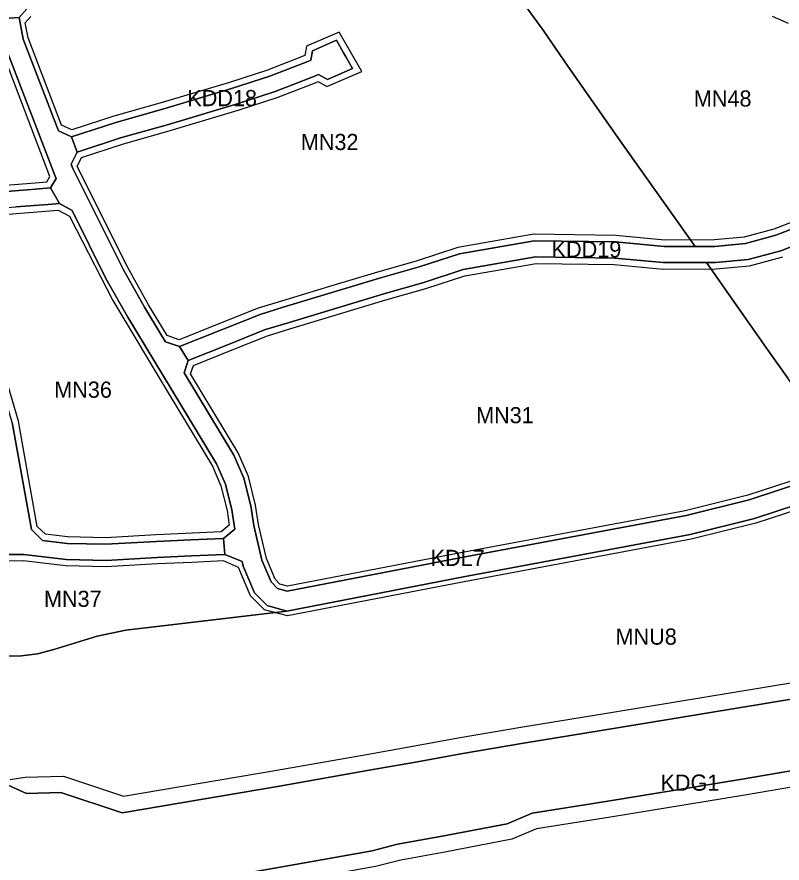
# Model space of a CAD drawing. Extents: x 7440055 to 7442242, y 5549003 to 5552256.
# Drawn here: x 7440932 to 7441405, y 5549569 to 5550092 of the extents above; entities that cross this region are included whole.
import ezdxf

# ---------------------------------------------------------------- set-up
doc = ezdxf.new("R2010")
doc.units = 0
for name, color, linetype in [('linie_rozgraniczajace', 7, 'Continuous'), ('linie_zabudowy_nieprzekraczalne', 7, 'Continuous'), ('oznaczenia_przeznaczen', 7, 'Continuous')]:
    doc.layers.add(name, color=color, linetype=linetype)

msp = doc.modelspace()

# ---------------------------------------------------------------- linework, layer by layer
at = {"layer": 'linie_rozgraniczajace'}
for points in [[(7441244.66, 5550101.57), (7441257.4, 5550083.89), (7441272.75, 5550061.72), (7441288.11, 5550039.55), (7441305.11, 5550015.41), (7441322.11, 5549991.27), (7441351.43, 5549950.16), (7441332.19, 5549950.12), (7441302.19, 5549952.9), (7441251.88, 5549953.71), (7441205.54, 5549945.54), (7441180.69, 5549937.47), (7441156.09, 5549930.49), (7441096.6, 5549912.51), (7441082.34, 5549908.12), (7441057.34, 5549898.15), (7441032.35, 5549888.19), (7441023.63, 5549891.17), (7441021.01, 5549895.49), (7441010.69, 5549912.54), (7440997.68, 5549935.61), (7440966.39, 5549998.44), (7440965.36, 5550001.13), (7440968.96, 5550008.55), (7440995.87, 5550017.35), (7441025.56, 5550025.67), (7441067.52, 5550038.25), (7441091.52, 5550046), (7441115.5, 5550055.3), (7441118.48, 5550056.6), (7441123.9, 5550053.49), (7441139.47, 5550060.24), (7441135, 5550067.98), (7441133.96, 5550069.96), (7441129.54, 5550077.73), (7441114.6, 5550071.26), (7441113.57, 5550065.36), (7441111.7, 5550064.56), (7441088.18, 5550055.43), (7441064.55, 5550047.8), (7441022.78, 5550035.28), (7440992.96, 5550026.92), (7440965.52, 5550017.95), (7440957.49, 5550021.69), (7440935.75, 5550078.45), (7440933.14, 5550091.88), (7440937.99, 5550097.18)], [(7441411.06, 5550092.87), (7441419.58, 5550088.95), (7441428.98, 5550084.13), (7441435.04, 5550080.83), (7441445.51, 5550074.75), (7441485.64, 5550051.12), (7441493.91, 5550042.46), (7441494.16, 5550031.09), (7441441.35, 5549976.89), (7441420.1, 5549964.26), (7441401.34, 5549957.05), (7441382.54, 5549951.99), (7441363.61, 5549950.18), (7441351.43, 5549950.16), (7441322.11, 5549991.27), (7441305.11, 5550015.41), (7441288.11, 5550039.55), (7441272.75, 5550061.72), (7441257.4, 5550083.89), (7441244.66, 5550101.57)], [(7440937.99, 5550097.18), (7440933.14, 5550091.88), (7440921.08, 5550091.06), (7440913.88, 5550095.55), (7440787.47, 5550086.98), (7440782.28, 5550081.64), (7440772.28, 5550080.96), (7440765.42, 5550085.49), (7440743.79, 5550084.03), (7440738.28, 5550083.8), (7440736.27, 5550083.77)], [(7440921.08, 5550091.06), (7440933.14, 5550091.88), (7440935.75, 5550078.45), (7440957.49, 5550021.69), (7440965.52, 5550017.95), (7440968.96, 5550008.55), (7440965.36, 5550001.13), (7440966.39, 5549998.44), (7440997.68, 5549935.61), (7441010.69, 5549912.54), (7441021.01, 5549895.49), (7441023.63, 5549891.17), (7441032.35, 5549888.19), (7441037.76, 5549879.58), (7441035.24, 5549871.98), (7441066.05, 5549821.08), (7441072.24, 5549806.85), (7441076.53, 5549789.57), (7441078.31, 5549777.44), (7441083.32, 5549756.08), (7441089.01, 5549742.53), (7441092.92, 5549738.59), (7441099.04, 5549736.87), (7441205.81, 5549757.44), (7441345.8, 5549783.58), (7441384.91, 5549793.35), (7441419.28, 5549804.6)], [(7440924.17, 5550075.14), (7440955.39, 5549993.61), (7440956.09, 5549992.21), (7440952.64, 5549986.34), (7440943.35, 5549985.58), (7440917.23, 5549983.48)], [(7441414.65, 5549790.45), (7441388.23, 5549781.81), (7441348.36, 5549771.85), (7441208.05, 5549745.65), (7441098.76, 5549724.49), (7441086.62, 5549727.89), (7441078.85, 5549735.74), (7441071.87, 5549752.37), (7441071.22, 5549755.14), (7441060.41, 5549759.56), (7441059.61, 5549769.53), (7441066.52, 5549775.2), (7441064.74, 5549787.25), (7441060.84, 5549802.98), (7441055.37, 5549815.55), (7441000.33, 5549906.48), (7440987.07, 5549929.99), (7440965.97, 5549972.37), (7440958.2, 5549976.76), (7440952.64, 5549986.34), (7440956.09, 5549992.21), (7440955.39, 5549993.61), (7440924.17, 5550075.14)], [(7440917.23, 5549983.48), (7440943.35, 5549985.58), (7440952.64, 5549986.34), (7440958.2, 5549976.76), (7440951.18, 5549976.19), (7440931.08, 5549974.56)], [(7441424.48, 5549955.23), (7441404.44, 5549947.53), (7441384.33, 5549942.11), (7441364.1, 5549940.19), (7441358.42, 5549940.18), (7441331.74, 5549940.12), (7441301.65, 5549942.91), (7441252.68, 5549943.69), (7441207.96, 5549935.82), (7441183.6, 5549927.9), (7441158.9, 5549920.9), (7441099.52, 5549902.95), (7441085.67, 5549898.68), (7441085.06, 5549898.5), (7441061.72, 5549889.13), (7441037.76, 5549879.58), (7441032.35, 5549888.19), (7441057.34, 5549898.15), (7441082.34, 5549908.12), (7441096.6, 5549912.51), (7441156.09, 5549930.49), (7441180.69, 5549937.47), (7441205.54, 5549945.54), (7441251.88, 5549953.71), (7441302.19, 5549952.9), (7441332.19, 5549950.12), (7441351.43, 5549950.16), (7441363.61, 5549950.18), (7441382.54, 5549951.99), (7441401.34, 5549957.05), (7441420.1, 5549964.26)], [(7441419.28, 5549804.6), (7441384.91, 5549793.35), (7441345.8, 5549783.58), (7441205.81, 5549757.44), (7441099.04, 5549736.87), (7441092.92, 5549738.59), (7441089.01, 5549742.53), (7441083.32, 5549756.08), (7441078.31, 5549777.44), (7441076.53, 5549789.57), (7441072.24, 5549806.85), (7441066.05, 5549821.08), (7441035.24, 5549871.98), (7441037.76, 5549879.58), (7441061.72, 5549889.13), (7441085.06, 5549898.5), (7441085.67, 5549898.68), (7441099.52, 5549902.95), (7441158.9, 5549920.9), (7441183.6, 5549927.9), (7441207.96, 5549935.82), (7441252.68, 5549943.69), (7441301.65, 5549942.91), (7441331.74, 5549940.12), (7441358.42, 5549940.18), (7441382.53, 5549905.82), (7441395.68, 5549887.23), (7441408.82, 5549868.65)], [(7440928.76, 5549841.19), (7440940.71, 5549774.91), (7440947.63, 5549768.24), (7440962.89, 5549766.41), (7440986.73, 5549765.88), (7441018.11, 5549767.68), (7441039.41, 5549768.65), (7441059.61, 5549769.53), (7441060.41, 5549759.56), (7441039.86, 5549758.66), (7441018.62, 5549757.69), (7440986.91, 5549755.88), (7440962.18, 5549756.42), (7440936, 5549759.56), (7440910.98, 5549759.5)], [(7440926.69, 5549696.68), (7440934.53, 5549696.82), (7440944.59, 5549697.98), (7440954.59, 5549700.82), (7440981.5, 5549708.94), (7440999.24, 5549712.67), (7441098.76, 5549724.49), (7441208.05, 5549745.65), (7441348.36, 5549771.85), (7441388.23, 5549781.81), (7441414.65, 5549790.45)], [(7440910.98, 5549759.5), (7440936, 5549759.56), (7440962.18, 5549756.42), (7440986.91, 5549755.88), (7441018.62, 5549757.69), (7441039.86, 5549758.66), (7441060.41, 5549759.56), (7441071.22, 5549755.14), (7441071.87, 5549752.37), (7441078.85, 5549735.74), (7441086.62, 5549727.89), (7441098.76, 5549724.49), (7440999.24, 5549712.67), (7440981.5, 5549708.94), (7440954.59, 5549700.82), (7440944.59, 5549697.98), (7440934.53, 5549696.82), (7440926.69, 5549696.68)], [(7440802.48, 5549567), (7440823.23, 5549572.15), (7440843.5, 5549575.3), (7440855.84, 5549576.74), (7440884.44, 5549597.32), (7440908.45, 5549606.4), (7440914.7, 5549614.65), (7440924.18, 5549617.76), (7440937.73, 5549611.73), (7440959.03, 5549612.31), (7440997, 5549599.66), (7441094.31, 5549616.16), (7441149.75, 5549626.01), (7441179.57, 5549631.34), (7441206.47, 5549636.19), (7441246.5, 5549643.08), (7441303.43, 5549652.3), (7441394.72, 5549667.37), (7441442.22, 5549675.26)], [(7441442.22, 5549675.26), (7441394.72, 5549667.37), (7441303.43, 5549652.3), (7441246.5, 5549643.08), (7441206.47, 5549636.19), (7441179.57, 5549631.34), (7441149.75, 5549626.01), (7441094.31, 5549616.16), (7440997, 5549599.66), (7440959.03, 5549612.31), (7440937.73, 5549611.73), (7440924.18, 5549617.76)], [(7441077.17, 5549562.92), (7441114.4, 5549569.57), (7441151.63, 5549576.22), (7441167.26, 5549580.22), (7441194.82, 5549585.27), (7441235.03, 5549592.94), (7441250.56, 5549599.46), (7441297.44, 5549606.92), (7441339.01, 5549613.71), (7441380.59, 5549620.51), (7441416.63, 5549626.68)], [(7441416.63, 5549626.68), (7441380.59, 5549620.51)], [(7441380.59, 5549620.51), (7441339.01, 5549613.71), (7441297.44, 5549606.92), (7441250.56, 5549599.46), (7441235.03, 5549592.94), (7441194.82, 5549585.27), (7441167.26, 5549580.22), (7441151.63, 5549576.22), (7441114.4, 5549569.57), (7441077.17, 5549562.92)]]:
    msp.add_lwpolyline(points, dxfattribs=at)
for points in [[(7440965.52, 5550017.95), (7440992.96, 5550026.92), (7441022.78, 5550035.28), (7441064.55, 5550047.8), (7441088.18, 5550055.43), (7441111.7, 5550064.56), (7441113.57, 5550065.36), (7441114.6, 5550071.26), (7441129.54, 5550077.73), (7441133.96, 5550069.96), (7441135, 5550067.98), (7441139.47, 5550060.24), (7441123.9, 5550053.49), (7441118.48, 5550056.6), (7441115.5, 5550055.3), (7441091.52, 5550046), (7441067.52, 5550038.25), (7441025.56, 5550025.67), (7440995.87, 5550017.35), (7440968.96, 5550008.55)], [(7441358.42, 5549940.18), (7441364.1, 5549940.19), (7441384.33, 5549942.11), (7441404.44, 5549947.53), (7441424.48, 5549955.23), (7441447.59, 5549968.97), (7441501.33, 5550023.93), (7441512.47, 5550024.21), (7441597.49, 5549942.15), (7441597.49, 5549930.9), (7441547.82, 5549887.51), (7441530.17, 5549873.25), (7441499.57, 5549847.44), (7441470.08, 5549827.43), (7441446.19, 5549815.48), (7441420.8, 5549851.6), (7441408.82, 5549868.65), (7441395.68, 5549887.23), (7441382.53, 5549905.82)], [(7440888.56, 5549966.4), (7440891.9, 5549971.51), (7440904.95, 5549972.51), (7440931.08, 5549974.56), (7440951.18, 5549976.19), (7440958.2, 5549976.76), (7440965.97, 5549972.37), (7440987.07, 5549929.99), (7441000.33, 5549906.48), (7441055.37, 5549815.55), (7441060.84, 5549802.98), (7441064.74, 5549787.25), (7441066.52, 5549775.2), (7441059.61, 5549769.53), (7441039.41, 5549768.65), (7441018.11, 5549767.68), (7440986.73, 5549765.88), (7440962.89, 5549766.41), (7440947.63, 5549768.24), (7440940.71, 5549774.91), (7440928.76, 5549841.19), (7440908.02, 5549911.96), (7440897.45, 5549940.84)]]:
    msp.add_lwpolyline(points, close=True, dxfattribs=at)
at = {"layer": 'linie_zabudowy_nieprzekraczalne'}
for points in [[(7441118.23, 5550052.13), (7441123.64, 5550049.03), (7441145.15, 5550058.33), (7441131.25, 5550082.83), (7441111.04, 5550074.08), (7441110.02, 5550068.27), (7441086.83, 5550059.2), (7441063.36, 5550051.62), (7441021.66, 5550039.12), (7440991.8, 5550030.75), (7440965.78, 5550022.24), (7440959.34, 5550025.24), (7440938.64, 5550079.28), (7440936.85, 5550088.53), (7440940.33, 5550092.33)], [(7441399, 5550092.55), (7441409.04, 5550088.3)], [(7440916.91, 5549987.47), (7440943.03, 5549989.57), (7440950.24, 5549990.15), (7440952.22, 5549993.51), (7440921.27, 5550074.31)], [(7441418.35, 5549967.87), (7441400.1, 5549960.86), (7441381.83, 5549955.94), (7441363.42, 5549954.18), (7441332.38, 5549954.12), (7441302.41, 5549956.9), (7441251.57, 5549957.71), (7441204.57, 5549949.43), (7441191.92, 5549945.32), (7441179.53, 5549941.3), (7441167.25, 5549937.82), (7441154.97, 5549934.33), (7441125.2, 5549925.34), (7441095.43, 5549916.34), (7441080.96, 5549911.88), (7441056.63, 5549902.18), (7441032.24, 5549892.45), (7441024.82, 5549894.99), (7441021.89, 5549899.83), (7441013.28, 5549914.05), (7441000.33, 5549937.02), (7440969.11, 5549999.7), (7440971.82, 5550005.28), (7440997.03, 5550013.52), (7441026.68, 5550021.83), (7441068.71, 5550034.43), (7441092.86, 5550042.23), (7441117.02, 5550051.6), (7441118.23, 5550052.13)], [(7441063.13, 5549777.59), (7441058.11, 5549773.47), (7441017.9, 5549771.67), (7440986.66, 5549769.89), (7440963.18, 5549770.4), (7440949.44, 5549772.05), (7440944.41, 5549776.89), (7440932.66, 5549842.11), (7440911.82, 5549913.21), (7440901.22, 5549942.18), (7440892.98, 5549965.86), (7440894.17, 5549967.67), (7440918.33, 5549969.52), (7440957.32, 5549972.66), (7440964.4, 5549968.79), (7440968.56, 5549960.44), (7440991.08, 5549916.78), (7441025.28, 5549859.47), (7441052.7, 5549814.17), (7441057.99, 5549802.02), (7441061.79, 5549786.66), (7441063.13, 5549777.59)], [(7441208.93, 5549931.92), (7441253, 5549939.69), (7441301.43, 5549938.91), (7441331.56, 5549936.12), (7441364.29, 5549936.19), (7441385.04, 5549938.16), (7441405.68, 5549943.72)], [(7441418.25, 5549807.42), (7441384.08, 5549796.23), (7441345.17, 5549786.51), (7441205.25, 5549760.39), (7441099.17, 5549739.95), (7441094.49, 5549741.26), (7441091.55, 5549744.23), (7441086.19, 5549757.01), (7441081.26, 5549778.01), (7441079.47, 5549790.15), (7441075.09, 5549807.81), (7441068.72, 5549822.46), (7441039.2, 5549871.23), (7441040.97, 5549876.56), (7441063.99, 5549885.73), (7441086.85, 5549894.86), (7441100.69, 5549899.12), (7441160.03, 5549917.06), (7441184.77, 5549924.08), (7441208.93, 5549931.92)], [(7441424.42, 5549790.5), (7441389.06, 5549778.93), (7441349, 5549768.92), (7441208.61, 5549742.71), (7441099.31, 5549721.54), (7441085.05, 5549725.22), (7441076.31, 5549734.05), (7441068.97, 5549751.52), (7441068.97, 5549751.52), (7441059.71, 5549755.53), (7441040.04, 5549754.66), (7441018.82, 5549753.7), (7440986.98, 5549751.88), (7440961.9, 5549752.42), (7440935.77, 5549755.56), (7440911.21, 5549755.5)], [(7440927.56, 5549620.28), (7440936.97, 5549621.71), (7440960.51, 5549622.35), (7440997.79, 5549609.94), (7441092.59, 5549626.01), (7441147.99, 5549635.86), (7441177.8, 5549641.18), (7441204.74, 5549646.04), (7441244.85, 5549652.94), (7441301.82, 5549662.16), (7441393.09, 5549677.24), (7441440.55, 5549685.12)], [(7441418.31, 5549616.82), (7441382.24, 5549610.65), (7441299.03, 5549597.04), (7441253.32, 5549589.77), (7441237.94, 5549583.32), (7441196.66, 5549575.44), (7441169.4, 5549570.45), (7441153.75, 5549566.44), (7441078.93, 5549553.07), (7441023.41, 5549543.16), (7440983.33, 5549524.98), (7440961.1, 5549518.84), (7440962.53, 5549517.42), (7440971.89, 5549499.42), (7440996.25, 5549356.45), (7440999.1, 5549354.55), (7441026.96, 5549360.92), (7441034.17, 5549364.81)]]:
    msp.add_lwpolyline(points, dxfattribs=at)

# ---------------------------------------------------------------- texts
at = {"layer": 'oznaczenia_przeznaczen'}
for s, p in [('KDD18', (7441037.21, 5550036.94)), ('MN48', (7441350.65, 5550036.67)), ('MN32', (7441107.46, 5550009.79)), ('KDD19', (7441262.65, 5549943.35)), ('MN36', (7440954.87, 5549856.52)), ('MN31', (7441215.9, 5549840.75)), ('KDL7', (7441187.78, 5549752.44)), ('MN37', (7440948.52, 5549727.11)), ('MNU8', (7441302.21, 5549703.74)), ('KDG1', (7441330.01, 5549613.38))]:
    msp.add_text(s, height=10, dxfattribs=at).set_placement(p)

doc.saveas('drawing.dxf')
